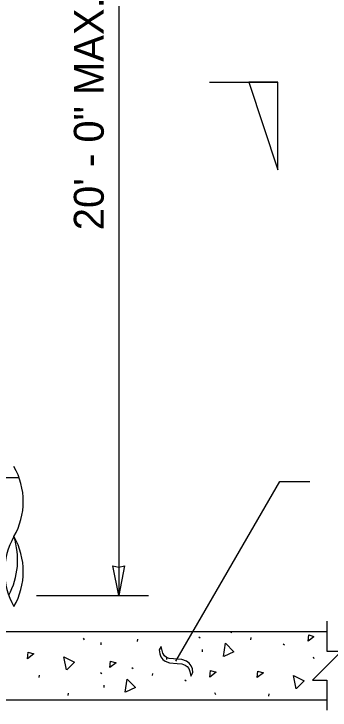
# Model space of a CAD drawing. Extents: x 99862 to 103151, y 100000 to 102076.
# Drawn here: x 102208.7 to 102377.7, y 100624.6 to 100997.1 of the extents above; entities that cross this region are included whole.
import ezdxf

# ---------------------------------------------------------------- set-up
doc = ezdxf.new("R2010")
doc.units = 0
for name, color, linetype in [('Level 1', 7, 'Continuous'), ('Level 15', 7, 'Continuous'), ('Level 19', 7, 'Continuous'), ('Level 20', 7, 'Continuous'), ('Level 6', 7, 'Continuous'), ('Level 9', 7, 'Continuous')]:
    doc.layers.add(name, color=color, linetype=linetype)

msp = doc.modelspace()

# ---------------------------------------------------------------- linework, layer by layer
at = {"layer": 'Level 1'}
for p, q in [((102171.16, 100666.66), (102376.12, 100666.66)), ((102147.16, 100629.98), (102376.02, 100629.98))]:
    msp.add_line(p, q, dxfattribs=at)
for centre, radius, start, end in [((102176.24, 100736.13), 37.43, 330, 30), ((102241.08, 100698.7), 37.43, 150, 210), ((102170.64, 100704.95), 40.01, 331.7011, 18.1584), ((102176.24, 100698.7), 37.43, 330, 30)]:
    msp.add_arc(centre, radius, start, end, dxfattribs=at)
at = {"layer": 'Level 15'}
for p, q in [((102264.7, 101204.48), (102264.7, 100685.98)), ((102295.32, 100650.7), (102350.87, 100746.92)), ((102350.87, 100746.92), (102366.87, 100746.92)), ((102220.71, 100685.98), (102280.7, 100685.98))]:
    msp.add_line(p, q, dxfattribs=at)
msp.add_lwpolyline([(102264.7, 100685.98), (102261.62, 100701.71), (102264.7, 100700.98), (102267.78, 100701.71)], close=True, dxfattribs=at)
msp.add_lwpolyline([(102376.07, 100672.07), (102376.07, 100656.07), (102383.81, 100656.07), (102368.33, 100640.58), (102376.07, 100640.58), (102376.07, 100624.58)], dxfattribs=at)
at = {"layer": 'Level 19'}
for p, q in [((102324.39, 100666.54), (102325.11, 100666.01)), ((102245.77, 100663.13), (102246.27, 100662.11)), ((102274.81, 100661.25), (102274.89, 100662.47)), ((102307.57, 100663.78), (102308.29, 100663.25)), ((102335.4, 100662.15), (102335.48, 100663.37)), ((102255.31, 100659.57), (102255.39, 100660.8)), ((102352.72, 100659.99), (102353.44, 100659.46)), ((102309.48, 100655.76), (102309.57, 100656.98)), ((102290.37, 100651.57), (102290.46, 100652.79)), ((102368.61, 100653.08), (102369.08, 100652.13)), ((102271.76, 100647.38), (102272.48, 100646.85)), ((102222.19, 100642.1), (102222.27, 100643.32)), ((102254.95, 100644.63), (102255.67, 100644.1)), ((102282.77, 100643), (102282.86, 100644.22)), ((102300.1, 100640.84), (102300.82, 100640.31)), ((102256.86, 100636.61), (102256.95, 100637.83)), ((102237.75, 100632.41), (102237.83, 100633.64)), ((102315.99, 100633.93), (102316.49, 100632.92)), ((102345.03, 100632.05), (102345.12, 100633.28))]:
    msp.add_line(p, q, dxfattribs=at)
for points in [[(102366.1, 100661.42), (102366.43, 100664.85), (102369.08, 100664.04)], [(102369.08, 100663.7), (102366.1, 100661.42)], [(102320.77, 100653.26), (102321.76, 100660.36), (102326.21, 100655.77), (102320.89, 100653.3)], [(102215.94, 100652.06), (102216.28, 100655.49), (102219.25, 100654.59), (102215.94, 100652.06)], [(102236.84, 100646.06), (102235.33, 100653.08), (102241.09, 100650.28), (102236.94, 100646.14)], [(102260.01, 100647.39), (102260.34, 100650.83), (102263.32, 100649.92), (102260.01, 100647.39)], [(102313.47, 100642.26), (102313.81, 100645.69), (102316.78, 100644.79), (102313.47, 100642.26)], [(102338.78, 100642.02), (102339.12, 100645.45), (102342.09, 100644.55), (102338.78, 100642.02)], [(102268.15, 100634.11), (102269.14, 100641.21), (102273.59, 100636.61), (102268.27, 100634.15)], [(102359.68, 100636.02), (102358.18, 100643.03), (102363.93, 100640.23), (102359.78, 100636.1)]]:
    msp.add_lwpolyline(points, dxfattribs=at)
at = {"layer": 'Level 20'}
for p, q in [((102287.32, 100658.61), (102286.27, 100656.78)), ((102288.31, 100655.05), (102287.32, 100658.61)), ((102286.27, 100656.78), (102286.63, 100654.67)), ((102286.63, 100654.67), (102287.27, 100653.01)), ((102289.18, 100653.65), (102288.31, 100655.05)), ((102287.27, 100653.01), (102288.23, 100651.71)), ((102288.23, 100651.71), (102289.56, 100650.7)), ((102290.26, 100652.73), (102289.18, 100653.65)), ((102289.56, 100650.7), (102291.85, 100649.81)), ((102291.67, 100652.2), (102290.26, 100652.73)), ((102294.08, 100652), (102291.67, 100652.2)), ((102298.48, 100651.63), (102294.08, 100652)), ((102301.03, 100650.7), (102298.48, 100651.63)), ((102302.43, 100649.63), (102301.03, 100650.7)), ((102291.85, 100649.81), (102295.94, 100649.54)), ((102295.94, 100649.54), (102298.48, 100649.32)), ((102298.48, 100649.32), (102300.29, 100648.69)), ((102300.29, 100648.69), (102301.34, 100647.86)), ((102301.34, 100647.86), (102302.14, 100646.77)), ((102303.45, 100648.26), (102302.43, 100649.63)), ((102304.08, 100646.58), (102303.45, 100648.26)), ((102302.14, 100646.77), (102302.76, 100645.15)), ((102302.76, 100645.15), (102303.28, 100642.78)), ((102303.28, 100642.78), (102304.34, 100644.61)), ((102304.34, 100644.61), (102304.08, 100646.58))]:
    msp.add_line(p, q, dxfattribs=at)
at = {"layer": 'Level 6'}
msp.add_line((102118.66, 100748.98), (102211.4, 100748.98), dxfattribs=at)
at = {"layer": 'Level 9'}
msp.add_line((102313.27, 100960.61), (102349.79, 100960.61), dxfattribs=at)
msp.add_lwpolyline([(102334.27, 100960.61), (102349.8, 100913.72), (102349.8, 100960.61)], close=True, dxfattribs=at)

# ---------------------------------------------------------------- texts
at = {"layer": 'Level 20'}
msp.add_text('20\' - 0" MAX.', height=16, rotation=90, dxfattribs=at).set_placement((102256.7, 100881.34))

doc.saveas('drawing.dxf')
